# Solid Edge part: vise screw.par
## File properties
Title: Vise Screw
Author: Deepak Maini
Template: Normal.par
Last saved by: Robert a Rhodes jr
Revision: 5
Application: Solid Edge
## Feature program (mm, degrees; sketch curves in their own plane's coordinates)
sketch for "unnamed RevolvedProtrusion 1" plane through (0, 0, 0) normal (0, -1, 0) x-axis (1, 0, 0)
  line (9.525, 77.2518) -> (9.525, 56.627)
  line (9.525, 56.627) -> (6.35, 56.627)
  line (6.35, 56.627) -> (6.35, 50.277)
  line (6.35, 50.277) -> (7.9375, 50.277)
  line (7.9375, 50.277) -> (7.9375, -49.7228)
  line (7.9375, -49.7228) -> (6.35, -49.7228)
  line (6.35, -49.7228) -> (6.35, -72.5828)
  line (6.35, -72.5828) -> (4.7625, -72.5828)
  line (4.7625, -72.5828) -> (4.7625, -75.1482)
  line (4.7625, -75.1482) -> (6.35, -75.1482)
  line (6.35, -75.1482) -> (6.35, -81.4982)
  line (6.35, -81.4982) -> (0, -81.4982)
  line (0, -81.4982) -> (0, 77.2518)
  line (0, 77.2518) -> (9.525, 77.2518)
revolve "unnamed RevolvedProtrusion 1" add finite 360 deg
sketch for "unnamed Hole 1" plane through (0, 0, 0) normal (0, -1, 0) x-axis (1, 0, 0)
  hole centre (0, 66.9394) bore radius 4.3688
hole "unnamed Hole 1" through
sketch for "unnamed Hole 2" plane through (0, 0, 0) normal (0, -1, 0) x-axis (1, 0, 0)
  hole centre (0, 66.9394) bore radius 4.3688
hole "unnamed Hole 2" through
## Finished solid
Body 1: solid body, 14 faces, 14 edges, 0 vertices.
  Faces by surface: cylinder 7, plane 7
  Edges by curve: circle 12, intersection 2
Bounding box of the edges (mm): 19.050 x 19.050 x 158.750, from (-9.525, -9.525, -81.4982) to (9.525, 9.525, 77.2518).
Cylindrical faces by radius (mm): R4.3688 x1, R4.7625 x1, R6.35 x3, R7.9375 x1, R9.525 x1
Planar faces by outward normal: +z 3, -z 4
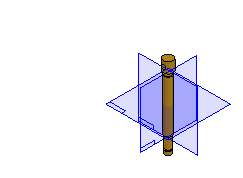
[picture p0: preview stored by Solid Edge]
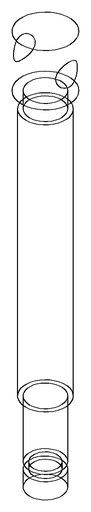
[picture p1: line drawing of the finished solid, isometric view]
